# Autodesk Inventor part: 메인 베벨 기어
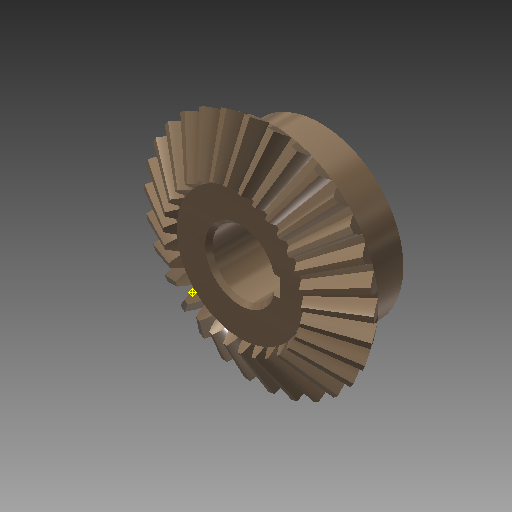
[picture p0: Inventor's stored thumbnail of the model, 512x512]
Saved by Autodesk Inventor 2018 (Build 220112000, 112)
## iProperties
Created: 2016-04
Part Number: 메인 베벨 기어
Material: 강철, 탄소
Document SubType Name: Modeling
Designer: mdu
Categories: <?xml version="1.0" encoding="UTF-16"?> <MemberInstance><Categories><FamilyTemplate><FamilyTemplateParameter ValueType="xs:double" Id="1" ObjectReferenceKey="da
Mass: 269.926 g
Surface Area: 108.837 cm^2
Volume: 34.2981 cm^3
Density: 7.87 g/cm^3
Appearance: 얼룩무늬
CustomPartVersion: 1
Author: mdu
Revision Number: 1
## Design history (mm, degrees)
node "맨 위 점"
node "메쉬 평면2"
sketch "톱니 본체 스케치"
  geometry: L1 (0, 0)-(28.669, -21.997); L2 (28.669, -21.997)-(31.109, -18.336); L3 (31.109, -18.336)-(0, 0); L4 (30, -20)-(0, 0); L5 (17.219, -13.212)-(18.685, -11.013); L6 (28.669, -21.997)-(17.219, -13.212); L7 (31.109, -18.336)-(18.685, -11.013); L8 (0, -39.387)-(0, 6.564) reference; L9 (0, -20)-(31.109, -20)
  constraints: 16 end point, 4 point on line, 3 perpendicular, 2 collinear, 1 horizontal alignment, 1 vertical alignment
  dimensions: "d0" = 60 diameter of L4.start L8 (= da_de); "d1" = 57.33744 diameter of L1.end L8 (= da_dfe); "d2" = 62.2188 diameter of L2.end L8 (= da_dae); "d3" = 14.4 distance between parallel lines of L2 L5 (= da_b); "d4" = 18.3359 vertical distance of L2.end L1.start (= da_ve)
revolve "톱니 본체" sketch "톱니 본체 스케치" stored, may be unused: angle "d5" = 90 deg
node "시작점"
node "톱니 평면"
sketch "시작 스케치"
  geometry: L1 (0, -23.505)-(0, 10.645) reference; L2 (-0.709, -2.928)-(0.709, -2.928); A1 r 19.188 centre (-19.457, -7.014) between (-0.709, -2.928) and (-3.232, 3.229); A2 r 19.188 centre (19.457, -7.014) between (3.232, 3.229) and (0.709, -2.928); A3 r 57.403 centre (0, -54.083) between (3.232, 3.229) and (-3.232, 3.229); 1 further point
  constraints: 6 point on circle, 3 centre point, 3 symmetric about line, 2 end point, 1 coincident, 1 perpendicular, 1 other
  dimensions: "d7" = 19.18795 radius of A1 (= fd_rr); "d8" = 19.45712 horizontal distance of point (0, -54.083) A1.centre (= fd_x); "d9" = 47.06905 vertical distance of point (0, -54.083) A1.centre (= fd_y); "d57" = 57.40327 radius of A3 (= 0.5 x fd_dva + 0.3 x da_he); "d58" = 51.15527 distance from line of A3.centre L2 (= 0.5 x fd_dva - 1.12 x da_he)
node "끝점"
  node "끝 평면"
sketch "3D 스케치 오른쪽"
  node "Helical Curve Right" dims "d65" = 229.90621 (computed from da_dm, da_delta, da_beta), "d66" = 31.5, "d67" = 60 (= da_de), "d68" = -9.82794 (= -da_delta), "d69" = 8.10972 (computed from fd_loft, da_delta)
node "끝 평면 오른쪽"
sketch "끝 스케치 오른쪽"
  geometry: L1 (0, -41.54)-(0, 13.178) reference; L2 (-0.422, -1.69)-(0.422, -1.69); A1 r 11.427 centre (-11.587, -4.123) between (-0.422, -1.69) and (-1.925, 1.977); A2 r 11.427 centre (11.587, -4.123) between (1.925, 1.977) and (0.422, -1.69); A3 r 34.184 centre (0, -32.153) between (1.925, 1.977) and (-1.925, 1.977); 1 further point
  constraints: 6 point on circle, 3 centre point, 3 symmetric about line, 2 end point, 1 coincident, 1 perpendicular, 1 other
  dimensions: "d70" = 11.58699 horizontal distance of A3.centre A1.centre (computed from fd_x, fd_ratio); "d71" = 28.03028 vertical distance of point (0, -32.153) A1.centre (computed from fd_y, fd_ratio); "d72" = 11.4267 radius of A1 (computed from fd_rr, fd_ratio); "d73" = 30.46369 distance from line of point (0, -32.153) L2 (computed from d58, fd_ratio); "d74" = 34.18446 radius of A3 (computed from d57, fd_ratio)
feature "로프트 오른쪽" sketch "끝 스케치 오른쪽" dims "d75" = 0, "d77" = 0, "d79" = 0, "d80" = 90 deg, "d85" = 20, "d92" = 90 deg, "d93" = 90 deg, "da_teethtype" = 0 [user parameter]
sketch "3D 스케치 왼쪽"
  node "Helical Curve Left" dims "d26" = 229.90621 (computed from da_dm, da_delta, da_beta), "d27" = 8.10972 (computed from fd_loft, da_delta), "d28" = 60 (= da_de), "d29" = -9.82794 (= -da_delta)
node "끝 평면 왼쪽"
sketch "끝 스케치 왼쪽" dims "d56" = 10.3728 (derived)
  geometry: L1 (0, -43.753)-(0, 15.405) reference; L2 (-0.422, -1.678)-(0.422, -1.678); A1 r 11.427 centre (-11.587, -4.111) between (-0.422, -1.678) and (-1.925, 1.988); A2 r 11.427 centre (11.587, -4.111) between (1.925, 1.988) and (0.422, -1.678); A3 r 34.184 centre (0, -32.142) between (1.925, 1.988) and (-1.925, 1.988); 2 further points; 1 other entity
  constraints: 6 point on circle, 3 centre point, 3 symmetric about line, 2 end point, 1 coincident, 2 other
  dimensions: "d30" = 11.4267 radius of A1 (computed from fd_rr, fd_ratio); "d31" = 11.58699 horizontal distance of point (0, -32.142) A1.centre (computed from fd_x, fd_ratio); "d32" = 28.03028 vertical distance of A1.centre point (0, -32.142) (computed from fd_y, fd_ratio); "d61" = 34.18446 radius of A3 (computed from d57, fd_ratio); "d62" = 30.46369 distance from line of point (0, -32.142) L2 (computed from d58, fd_ratio)
feature "로프트 왼쪽" sketch "끝 스케치 왼쪽" dims "d35" = 0, "d37" = 0, "d39" = 0, "d40" = 90 deg, "d84" = 10, "d90" = 90 deg, "d91" = 90 deg, "da_teethtype" = 0 [user parameter]
sketch "본체 스케치"
  geometry: L1 (0, -35.038)-(0, -19.531) reference; L2 (28.669, -21.997)-(17.219, -13.212) reference; L3 (17.219, -13.212)-(0, -13.212); L4 (28.669, -21.997)-(0, -21.997)
  constraints: 4 end point, 2 perpendicular, 2 point on line
revolve "본체 고정" sketch "본체 스케치" stored, may be unused: angle "d46" = 90 deg
feature "피치 지름" dims angle "d47" = 90 deg
sketch "스케치8"
  geometry: C1 r 22.5 at (0, 0); 1 further point
  constraints: 1 centre point, 1 coincident
  dimensions: "d94" = 45 diameter of C1
extrude "돌출1" join sketch "스케치8" distance "d95" = 13; taper "d96" = 0 deg
sketch "스케치9"
  geometry: 1 further point
hole "구멍1" sketch "스케치9" at (0, 0) diameter "d97" = 17; stored, may be unused: countersink angle "d101" = 90 deg, drill point angle "d103" = 118 deg; dims "d98" = 6, "d99" = 4, "d100" = 2, "d102" = 8
sketch "스케치10"
  geometry: L1 (8.124, 2.5)-(10.8, 2.5); L2 (10.8, 2.5)-(10.8, -2.5); L3 (10.8, -2.5)-(8.124, -2.5); A1 r 8.5 centre (0, 0) between (8.124, 2.5) and (8.124, -2.5) reference; 1 further point
  constraints: 6 end point, 2 parallel, 2 point on circle, 1 horizontal, 1 perpendicular
  dimensions: "d104" = 5 distance of L1.end L2.end; "d112" = 19.3 dimension on A1 L2
extrude "돌출2" cut sketch "스케치10" extent not by distance; stored distance "d106" = 10; taper "d107" = 0 deg
chamfer "모따기1" distance "d108" = 1; stored, may be unused: second distance "d109" = 2, angle "d110" = 45 deg
fillet "모깎기1" dims "d111" = 2
body "Solid1"
feature "로프트" dims "d17" = 0, "d18" = 90 deg, "d19" = 0, "d20" = 90 deg, "d89" = 0, "da_teethtype" = 0 [user parameter]
pattern_circular "원형 패턴" dims angle "d22" = 360 deg, "d88" = 0, "da_teethtype" = 0 [user parameter]
pattern_circular "원형 패턴 오른쪽" dims angle "d82" = 360 deg, "da_teethtype" = 0 [user parameter]
pattern_circular "원형 패턴 왼쪽" dims angle "d42" = 360 deg, "da_teethtype" = 0 [user parameter]
sketch "끝 스케치"
  geometry: L1 (0, -15.359)-(0, 6.983) reference; L2 (-0.422, -1.69)-(0.422, -1.69); A1 r 11.427 centre (-11.587, -4.123) between (-0.422, -1.69) and (-1.925, 1.977); A2 r 11.427 centre (11.587, -4.123) between (1.925, 1.977) and (0.422, -1.69); A3 r 34.184 centre (0, -32.153) between (1.925, 1.977) and (-1.925, 1.977); 1 further point
  constraints: 6 point on circle, 3 centre point, 3 symmetric about line, 2 end point, 1 coincident, 1 other
  dimensions: "d12" = 11.4267 radius of A1 (computed from fd_rr, fd_ratio); "d15" = 11.58699 horizontal distance of A1.centre point (0, -32.153) (computed from fd_x, fd_ratio); "d16" = 28.03028 vertical distance of A1.centre point (0, -32.153) (computed from fd_y, fd_ratio); "d59" = 34.18446 radius of A3 (computed from d57, fd_ratio); "d60" = 30.46369 distance from line of A3.centre L2 (computed from d58, fd_ratio)
sketch "Sketch6"
  geometry: L1 (30, -20)-(0, 0) reference; L2 (0, -37.8)-(0, 6.3) reference
body "Srf1"
other parameters: "da_b" = 14.4 [user parameter; used in 2 equation terms], "da_de" = 60 [user parameter; used in 4 equation terms], "da_dae" = 62.2188 [user parameter; used in 2 equation terms], "da_dfe" = 57.33744 [user parameter; used in 1 equation term], "da_le" = 36.05551 [user parameter; used in 1 equation term], "da_omega" = 90 deg [user parameter; used in 1 equation term], "da_beta" = 0 [user parameter; used in 2 equation terms], "da_delta" = 9.82794 [user parameter; used in 8 equation terms], "da_alpha" = 20 deg [user parameter; used in 2 equation terms], "da_he" = 4.4 [user parameter; used in 4 equation terms], "da_ve" = 18.3359 [user parameter; used in 1 equation term], "fd_dv" = 108.16654 (computed from da_de, da_delta) [user parameter; used in 1 equation term], "fd_dva" = 112.16654 (computed from da_dae, da_delta) [user parameter; used in 3 equation terms], "fd_dvb" = 101.6433 (computed from fd_dv, da_alpha) [user parameter; used in 2 equation terms], "da_zv" = 540.83269 [user parameter; used in 1 equation term], "fd_loft" = 14.62 (= da_b + 0.05 x da_he) [user parameter; used in 4 equation terms], "fd_ratio" = 5.95514 (computed from da_le, fd_loft) [user parameter; used in 15 equation terms], "fd_rr" = 19.18795 (computed from fd_dd, fd_dvb) [user parameter; used in 6 equation terms], "fd_angle" = 0.29367 (computed from da_zv) [user parameter; used in 4 equation terms], "fd_x1" = 1.58802 (computed from da_dvw, fd_angle) [user parameter; used in 1 equation term], "fd_y1" = 54.05995 (computed from da_dvw, fd_angle) [user parameter; used in 1 equation term], "fd_x2" = 17.8691 (computed from fd_rr, fd_angle2, fd_angle) [user parameter; used in 1 equation term], "fd_y2" = 6.9909 (computed from fd_rr, fd_angle2, fd_angle) [user parameter; used in 1 equation term], "fd_x" = 19.45712 (= fd_x1 + fd_x2) [user parameter; used in 4 equation terms], "fd_y" = 47.06905 (= fd_y1 - fd_y2) [user parameter; used in 4 equation terms], "fd_angle2" = 3.43555 (computed from fd_dvb, fd_dd, da_alpha) [user parameter; used in 2 equation terms], "fd_dd" = 108.64654 (= fd_dva - 0.8 x da_he) [user parameter; used in 2 equation terms], "da_dvw" = 108.16654 [user parameter; used in 2 equation terms], "d11" = 14.62 (= fd_loft), "da_dm" = 48.01848 [user parameter; used in 2 equation terms], "da_x" = 0 [user parameter], "da_m" = 2 [user parameter], "d48" = 0, "d49" = 0, "d50" = 90 deg (= da_omega), "d51" = 6 deg (computed from da_z), "d52" = 0, "d53" = 0, "d54" = 0
